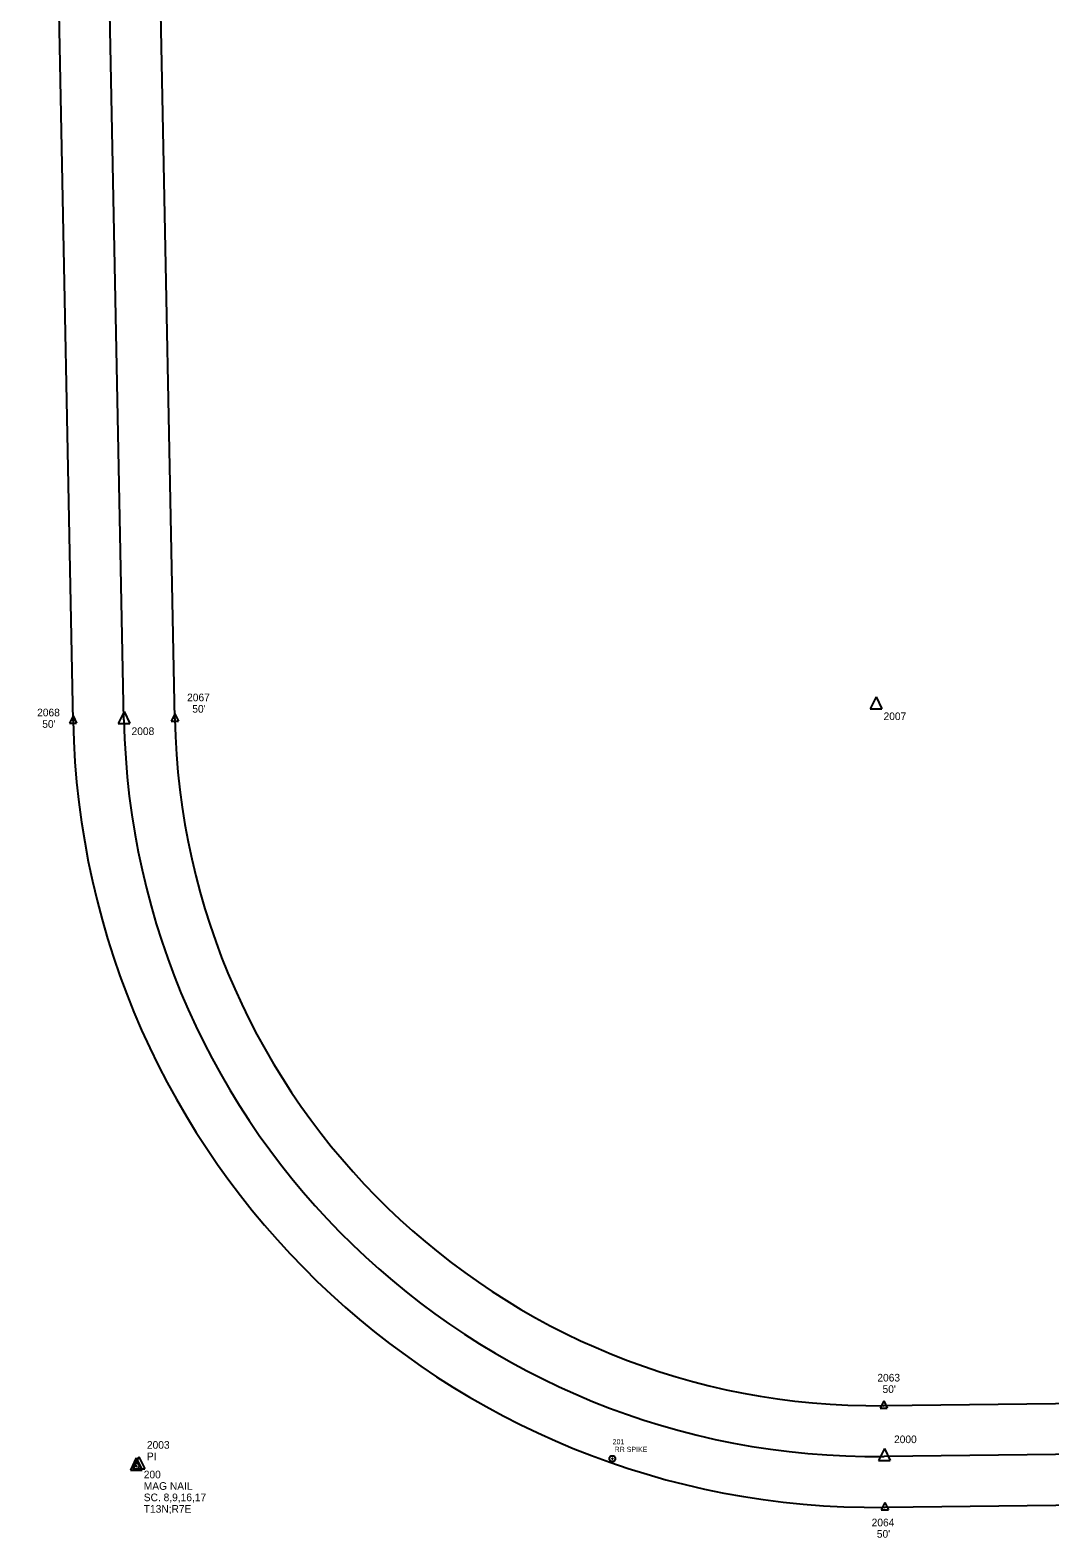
# Model space of a CAD drawing. Extents: x 1799493 to 1803621, y 522869 to 525846.
# Drawn here: x 1799526 to 1800528, y 522880 to 524363 of the extents above; entities that cross this region are included whole.
import ezdxf

# ---------------------------------------------------------------- set-up
doc = ezdxf.new("R2010")
doc.units = 0
for name, color, linetype in [('S_CAL_CORNER', 7, 'Continuous'), ('S_CAL_CORNER_ANNOT', 7, 'Continuous'), ('S_EXIST_ROW', 7, 'Continuous'), ('S_EXIST_ROW_ANNOT', 7, 'Continuous'), ('S_EXISTING_ALIGNMENT', 7, 'Continuous'), ('S_IRON_PIN', 7, 'Continuous'), ('S_IRON_PIN_ANNOT', 7, 'Continuous')]:
    doc.layers.add(name, color=color, linetype=linetype)

msp = doc.modelspace()

# ---------------------------------------------------------------- linework, layer by layer
at = {"layer": 'S_CAL_CORNER'}
for p, q in [((1800357.2, 523707.6), (1800351.3, 523695.7)), ((1800351.3, 523695.7), (1800363, 523695.7)), ((1800357.2, 523707.6), (1800363, 523695.7)), ((1799618, 523692.9), (1799612.1, 523681.1)), ((1799618, 523692.9), (1799612.1, 523681.1)), ((1799612.1, 523681.1), (1799623.8, 523681.1)), ((1799612.1, 523681.1), (1799623.8, 523681.1)), ((1799618, 523692.9), (1799623.8, 523681.1)), ((1799618, 523692.9), (1799623.8, 523681.1)), ((1800365.4, 522968.3), (1800359.5, 522956.5)), ((1800365.4, 522968.3), (1800359.5, 522956.5)), ((1800365.4, 522968.3), (1800371.2, 522956.5)), ((1800365.4, 522968.3), (1800371.2, 522956.5)), ((1799630, 522958.9), (1799624.2, 522947)), ((1799630, 522958.9), (1799624.2, 522947)), ((1799630, 522958.9), (1799624.2, 522947)), ((1799630, 522958.9), (1799624.2, 522947)), ((1799632.5, 522960.1), (1799626.6, 522948.3)), ((1799630, 522958.9), (1799635.9, 522947)), ((1799630, 522958.9), (1799635.9, 522947)), ((1799630, 522958.9), (1799635.9, 522947)), ((1799630, 522958.9), (1799635.9, 522947)), ((1799632.5, 522960.1), (1799638.3, 522948.3)), ((1800359.5, 522956.5), (1800371.2, 522956.5)), ((1800359.5, 522956.5), (1800371.2, 522956.5)), ((1799624.2, 522947), (1799635.9, 522947)), ((1799624.2, 522947), (1799635.9, 522947)), ((1799624.2, 522947), (1799635.9, 522947)), ((1799624.2, 522947), (1799635.9, 522947)), ((1799626.6, 522948.3), (1799638.3, 522948.3))]:
    msp.add_line(p, q, dxfattribs=at)
at = {"layer": 'S_EXIST_ROW'}
for p, q in [((1799567.9, 523684), (1799525.7, 525816.6)), ((1799667.9, 523685.9), (1799625.7, 525818.5)), ((1801600.5, 523024.1), (1800364.7, 523010.3)), ((1801601.6, 522924.1), (1800365.9, 522910.3))]:
    msp.add_line(p, q, dxfattribs=at)
for radius in [789.3, 689.3]:
    msp.add_arc((1800357.1, 523699.6), radius, 181.1334, 270.6378, dxfattribs=at)
at = {"layer": 'S_EXIST_ROW_ANNOT'}
for p, q in [((1799567.9, 523688.7), (1799564.4, 523681.6)), ((1799564.4, 523681.6), (1799571.4, 523681.6)), ((1799567.9, 523688.7), (1799571.4, 523681.6)), ((1799567.9, 523684), (1799567.9, 523684)), ((1799667.9, 523690.7), (1799664.4, 523683.6)), ((1799664.4, 523683.6), (1799671.4, 523683.6)), ((1799667.9, 523690.7), (1799671.4, 523683.6)), ((1799667.9, 523685.9), (1799667.9, 523685.9)), ((1800364.8, 523015), (1800361.2, 523008)), ((1800364.8, 523015), (1800368.2, 523008)), ((1800361.2, 523008), (1800368.2, 523008)), ((1800364.7, 523010.3), (1800364.7, 523010.3)), ((1800365.9, 522915), (1800362.3, 522908)), ((1800365.9, 522915), (1800369.4, 522908)), ((1800365.9, 522910.3), (1800365.9, 522910.3)), ((1800362.3, 522908), (1800369.4, 522908))]:
    msp.add_line(p, q, dxfattribs=at)
for centre, radius in [((1799567.9, 523684), 0.12), ((1799567.9, 523684), 0.06), ((1799667.9, 523685.9), 0.12), ((1799667.9, 523685.9), 0.06), ((1800364.7, 523010.3), 0.12), ((1800364.7, 523010.3), 0.06), ((1800365.9, 522910.3), 0.12), ((1800365.9, 522910.3), 0.06)]:
    msp.add_circle(centre, radius, dxfattribs=at)
at = {"layer": 'S_EXISTING_ALIGNMENT'}
for p, q in [((1799617.9, 523684.9), (1799575.7, 525817.6)), ((1802031.3, 522978.9), (1800365.3, 522960.3))]:
    msp.add_line(p, q, dxfattribs=at)
msp.add_arc((1800357.1, 523699.6), 739.3, 181.1334, 270.6378, dxfattribs=at)
at = {"layer": 'S_IRON_PIN'}
for centre, radius in [((1799629.9, 522950.9), 2.91), ((1800098, 522958.2), 2.91), ((1800098, 522958.2), 0.411), ((1800098, 522958.2), 0.262), ((1800098, 522958.2), 0.212), ((1800098, 522958.2), 0.145), ((1800098, 522958.2), 0.0581), ((1800098, 522958.2), 0.0822), ((1799629.9, 522950.9), 0.411), ((1799629.9, 522950.9), 0.212), ((1799629.9, 522950.9), 0.262), ((1799629.9, 522950.9), 0.145), ((1799629.9, 522950.9), 0.0822), ((1799629.9, 522950.9), 0.0581)]:
    msp.add_circle(centre, radius, dxfattribs=at)

# ---------------------------------------------------------------- texts
at = {"layer": 'S_CAL_CORNER_ANNOT'}
for s, p in [('2007', (1800364.6, 523684.6)), ('2008', (1799625.4, 523669.9)), ('2003', (1799640.5, 522968)), ('2000', (1800374.9, 522973.5)), ('PI', (1799640.5, 522956.7))]:
    msp.add_text(s, height=7.5, dxfattribs=at).set_placement(p)
at = {"layer": 'S_EXIST_ROW_ANNOT'}
for s, p in [('2067', (1799680, 523703.1)), ('2068', (1799532.6, 523688.3)), ("50'", (1799685.1, 523691.9)), ("50'", (1799537.6, 523677)), ('2063', (1800358.5, 523034.1)), ("50'", (1800363.6, 523022.9)), ('2064', (1800352.9, 522891.7)), ("50'", (1800358, 522880.5))]:
    msp.add_text(s, height=7.5, dxfattribs=at).set_placement(p)
at = {"layer": 'S_IRON_PIN_ANNOT'}
for s, height, p in [('201', 5, (1800098.3, 522972.4)), (' RR SPIKE', 5, (1800098.3, 522964.9)), ('200', 7.5, (1799637.4, 522938.9)), ('SC. 8,9,16,17', 7.5, (1799637.4, 522916.4)), ('MAG NAIL', 7.5, (1799637.4, 522927.6)), ('T13N;R7E', 7.5, (1799637.4, 522905.1))]:
    msp.add_text(s, height=height, dxfattribs=at).set_placement(p)

doc.saveas('drawing.dxf')
